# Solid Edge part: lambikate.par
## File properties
Title: lambikate
Author: Stella-Marii
Template: Iso Metric Part.par
Last saved by: Stella-Marii
Revision: 6
Application: Solid Edge
Document Number: 20
Density: 1190,000 kg/m^3
Accuracy: 0,990
Username: Stella-Marii
Material: Polycarbonate
Face Style: Red
Fill Style: ANSI34(Plastic)
Virtual Style: Red (Shiny)
Grouping: Non-metals\Plastics
LibraryName: Materials
Coef. of Thermal Exp: 6.8e-05
Thermal Conductivity: 2.3
Specific Heat: 1265.0
Modulus of Elasticity: 2240796025.0
Poisson's Ratio: 0.35
Yield Stress: 58605434.5
Ultimate Stress: 0.0
Elongation: 0.0
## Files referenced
..\scooter.asm
@C:\Users\Stella-Marii\DATA\KOOL\Solid Edge - scooter\scooter.asm
C:\Users\Stella-Marii\DATA\KOOL\Solid Edge - scooter\lenksu-toru ühendus.psm
hendus.psm
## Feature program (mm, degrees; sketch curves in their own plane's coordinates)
sketch for "unnamed Protrusion 1" plane through (0, 0, 0) normal (0, 0, 1) x-axis (1, 0, 0)
  circle centre (0, 0) radius 22.5
extrude "unnamed Protrusion 1" add finite 45.8156 along +normal
sketch for "ExtrudedCutout_1" plane through (0, 0, 0) normal (1, 0, 0) x-axis (0, 1, 0)
  circle centre (0.0335, 18.7509) radius 15
extrude "ExtrudedCutout_1" cut finite 83.6529 symmetric
sketch for "ExtrudedCutout_2" plane through (0, 0, 0) normal (0, -1, 0) x-axis (1, 0, 0)
  line (-42.0119, -11.3033) -> (11.1847, -11.3033)
  line (11.1847, -11.3033) -> (11.1847, 43.3161)
  line (11.1847, 43.3161) -> (-42.0119, 43.3161)
  line (-42.0119, 43.3161) -> (-42.0119, -11.3033)
extrude "ExtrudedCutout_2" cut finite 48.5377 symmetric
thinwall "Thinwall_1"  Thickness = 1 mm
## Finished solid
Body 1: solid body, 5 faces, 4 edges, 0 vertices.
  Faces by surface: cylinder 4, plane 1
  Edges by curve: circle 2, intersection 2
Bounding box of the edges (mm): 11.315 x 30.000 x 30.000, from (11.1847, -14.9665, 3.7509) to (22.5, 15.0335, 33.7509).
Cylindrical faces by radius (mm): R14 x1, R15 x1, R21.5 x1, R22.5 x1
Planar faces by outward normal: -x 1
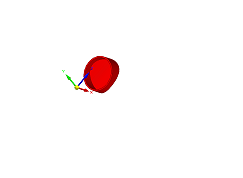
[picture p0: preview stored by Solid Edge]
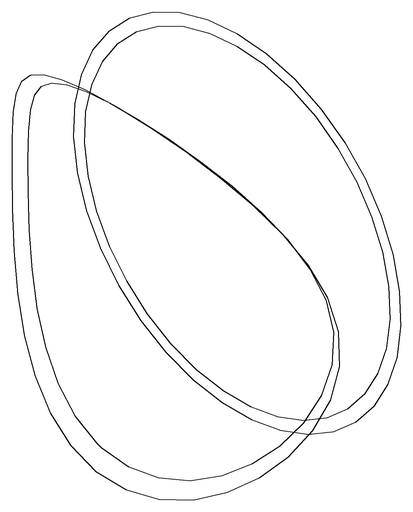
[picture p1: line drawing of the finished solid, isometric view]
